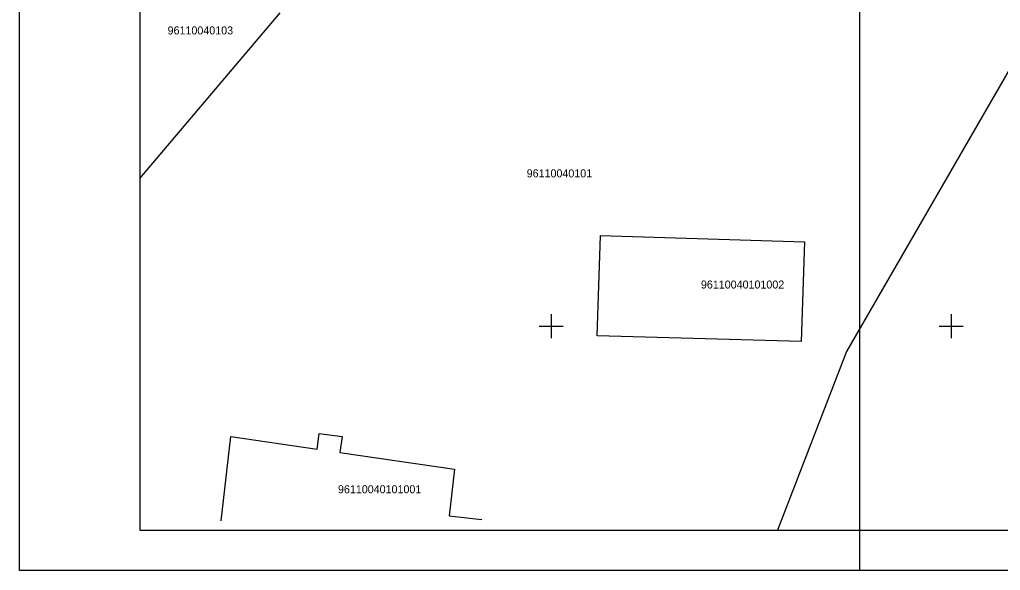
# Model space of a CAD drawing. Extents: x 561134 to 561329, y 413819 to 414116.
# Drawn here: x 561133.6 to 561256.1, y 413819.5 to 413888.3 of the extents above; entities that cross this region are included whole.
import ezdxf

# ---------------------------------------------------------------- set-up
doc = ezdxf.new("R2010")
doc.units = 0
for name, color, linetype in [('BUVE_EKAS_UZMR_####_#', 7, 'Continuous'), ('BUVE_EKAS_UZMR_TKST_#', 7, 'Continuous'), ('GEOD_ELEM_####_####_#', 7, 'Continuous'), ('RAMI_PLAN_####_TKST_#', 7, 'Continuous'), ('ROBZ_UZMR_####_####_#', 7, 'Continuous'), ('ROBZ_UZMR_####_TKST_#', 7, 'Continuous')]:
    doc.layers.add(name, color=color, linetype=linetype)

msp = doc.modelspace()

# ---------------------------------------------------------------- linework, layer by layer
at = {"layer": 'BUVE_EKAS_UZMR_####_#'}
for p, q in [((561205.76, 413848.82), (561206.16, 413861.34)), ((561206.16, 413861.34), (561231.67, 413860.55)), ((561231.67, 413860.55), (561231.24, 413848.08)), ((561231.24, 413848.08), (561205.76, 413848.82)), ((561158.77, 413825.69), (561159.97, 413836.21)), ((561159.97, 413836.21), (561170.74, 413834.65)), ((561170.74, 413834.65), (561171.02, 413836.6)), ((561171.02, 413836.6), (561173.89, 413836.23)), ((561173.89, 413836.23), (561173.6, 413834.23)), ((561173.6, 413834.23), (561187.91, 413832.16)), ((561187.91, 413832.16), (561187.25, 413826.31)), ((561187.25, 413826.31), (561191.33, 413825.86))]:
    msp.add_line(p, q, dxfattribs=at)
at = {"layer": 'GEOD_ELEM_####_####_#'}
for p, q in [((561200, 413851.5), (561200, 413850)), ((561250, 413851.5), (561250, 413850)), ((561198.5, 413850), (561200, 413850)), ((561200, 413850), (561200, 413848.5)), ((561200, 413850), (561201.5, 413850)), ((561248.5, 413850), (561250, 413850)), ((561250, 413850), (561250, 413848.5)), ((561250, 413850), (561251.5, 413850))]:
    msp.add_line(p, q, dxfattribs=at)
at = {"layer": 'RAMI_PLAN_####_TKST_#'}
for p, q in [((561133.58, 413819.5), (561133.58, 413968)), ((561238.58, 413819.5), (561238.58, 413968)), ((561328.58, 413819.5), (561133.58, 413819.5))]:
    msp.add_line(p, q, dxfattribs=at)
msp.add_lwpolyline([(561148.58, 414111.5), (561148.58, 413824.5), (561323.58, 413824.5), (561323.58, 414111.5)], close=True, dxfattribs=at)
at = {"layer": 'ROBZ_UZMR_####_####_#'}
for p, q in [((561277.05, 413916.42), (561236.89, 413846.84)), ((561148.58, 413868.46), (561166.12, 413889.15)), ((561236.89, 413846.84), (561228.26, 413824.5))]:
    msp.add_line(p, q, dxfattribs=at)

# ---------------------------------------------------------------- texts
at = {"layer": 'BUVE_EKAS_UZMR_TKST_#'}
for s, p in [('96110040101002', (561218.71, 413854.71)), ('96110040101001', (561173.36, 413829.13))]:
    msp.add_text(s, height=1, dxfattribs=at).set_placement(p)
at = {"layer": 'ROBZ_UZMR_####_TKST_#'}
for s, p in [('96110040103', (561152.07, 413886.46)), ('96110040101', (561196.94, 413868.6))]:
    msp.add_text(s, height=1, dxfattribs=at).set_placement(p)

doc.saveas('drawing.dxf')
